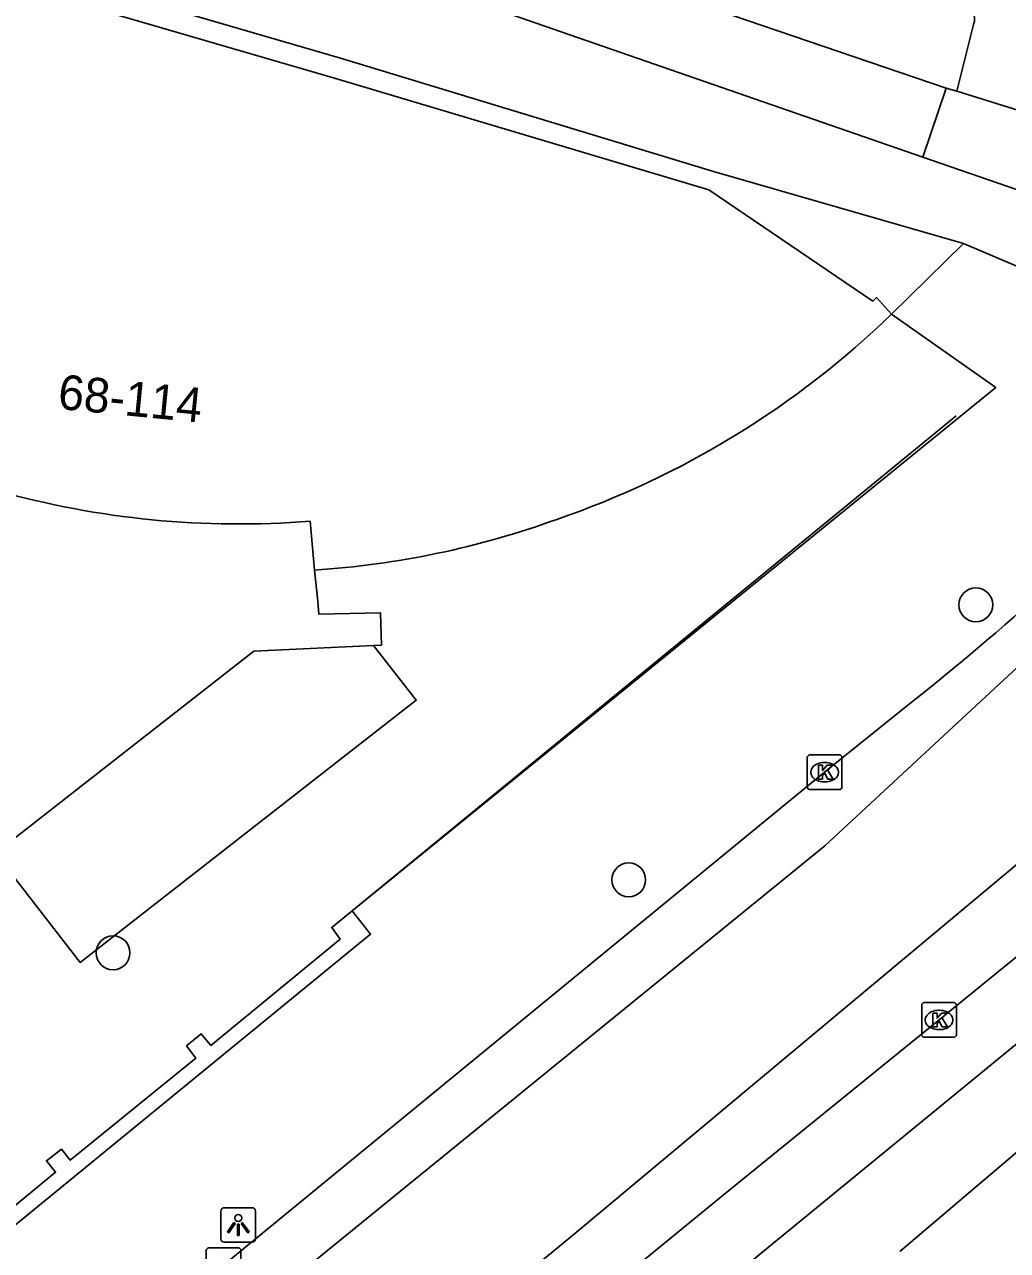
# Model space of a CAD drawing. Extents: x 161771 to 163125, y 382479 to 383177.
# Drawn here: x 162119.81 to 162148.2, y 383036.32 to 383071.72 of the extents above; entities that cross this region are included whole.
import ezdxf

# ---------------------------------------------------------------- set-up
doc = ezdxf.new("R2010")
doc.units = 0
for name, color, linetype in [('IMGEO_Boom', 7, 'Continuous'), ('IMGEO_Fietspad_gesloten', 7, 'Continuous'), ('IMGEO_Fietspad_open', 7, 'Continuous'), ('IMGEO_Groenvoorziening', 7, 'Continuous'), ('IMGEO_Hek', 7, 'Continuous'), ('IMGEO_Kolk', 7, 'Continuous'), ('IMGEO_Lichtpunt', 7, 'Continuous'), ('IMGEO_Muur', 7, 'Continuous'), ('IMGEO_Pand', 7, 'Continuous'), ('IMGEO_Pand_nummerreeks', 7, 'Continuous'), ('IMGEO_Rijbaan_lokaal_gesloten', 7, 'Continuous'), ('IMGEO_Voetpad_open', 7, 'Continuous')]:
    doc.layers.add(name, color=color, linetype=linetype)

msp = doc.modelspace()

# ---------------------------------------------------------------- linework, layer by layer
at = {"layer": 'IMGEO_Boom'}
for centre in [(162147.284, 383054.963), (162137.26, 383047.022), (162122.368, 383044.915)]:
    msp.add_circle(centre, 0.489, dxfattribs=at)
at = {"layer": 'IMGEO_Fietspad_gesloten'}
for points in [[(162114.9, 383079.294), (162127.757, 383076.182), (162129.761, 383075.563), (162130.935, 383075.168), (162146.429, 383069.887)], [(162145.752, 383067.892), (162131.194, 383072.949)], [(162146.429, 383069.887), (162145.752, 383067.892)]]:
    msp.add_lwpolyline(points, dxfattribs=at)
at = {"layer": 'IMGEO_Fietspad_open'}
for points in [[(162146.429, 383069.887), (162146.737, 383069.793)], [(162149.796, 383068.845), (162146.737, 383069.793)], [(162153.035, 383065.378), (162145.752, 383067.892)]]:
    msp.add_lwpolyline(points, dxfattribs=at)
at = {"layer": 'IMGEO_Groenvoorziening'}
msp.add_lwpolyline([(162129.888, 383053.79), (162131.122, 383052.209), (162121.422, 383044.636), (162118.96, 383047.789)], dxfattribs=at)
at = {"layer": 'IMGEO_Hek'}
msp.add_lwpolyline([(162129.276, 383046.131), (162146.715, 383060.424)], dxfattribs=at)
at = {"layer": 'IMGEO_Kolk'}
for p, q in [((162142.417, 383049.703), (162142.417, 383050.555)), ((162142.492, 383050.629), (162143.344, 383050.629)), ((162143.418, 383050.555), (162143.418, 383049.703)), ((162142.905, 383050.409), (162142.93, 383050.409)), ((162142.928, 383049.849), (162142.903, 383049.849)), ((162143.344, 383049.629), (162142.492, 383049.629)), ((162145.797, 383043.475), (162146.649, 383043.475)), ((162145.722, 383042.549), (162145.722, 383043.401)), ((162146.21, 383043.255), (162146.235, 383043.255)), ((162146.723, 383043.401), (162146.723, 383042.549)), ((162146.649, 383042.475), (162145.797, 383042.475)), ((162146.233, 383042.695), (162146.208, 383042.695)), ((162125.136, 383036.392), (162125.988, 383036.392)), ((162125.061, 383035.466), (162125.061, 383036.318)), ((162126.062, 383036.318), (162126.062, 383035.466))]:
    msp.add_line(p, q, dxfattribs=at)
for points in [[(162142.417, 383049.703), (162142.417, 383050.555)], [(162142.492, 383050.629), (162143.344, 383050.629)], [(162143.418, 383050.555), (162143.418, 383049.703)], [(162142.738, 383050.329), (162142.861, 383050.329), (162142.861, 383050.178), (162142.991, 383050.329), (162143.155, 383050.329), (162143.009, 383050.178), (162143.162, 383049.929), (162143.01, 383049.929), (162142.925, 383050.093), (162142.861, 383050.026), (162142.861, 383049.929), (162142.738, 383049.929), (162142.738, 383050.329)], [(162143.344, 383049.629), (162142.492, 383049.629)], [(162145.797, 383043.475), (162146.649, 383043.475)], [(162145.722, 383042.549), (162145.722, 383043.401)], [(162146.043, 383043.175), (162146.166, 383043.175), (162146.166, 383043.024), (162146.296, 383043.175), (162146.46, 383043.175), (162146.314, 383043.024), (162146.467, 383042.775), (162146.315, 383042.775), (162146.23, 383042.939), (162146.166, 383042.872), (162146.166, 383042.775), (162146.043, 383042.775), (162146.043, 383043.175)], [(162146.723, 383043.401), (162146.723, 383042.549)], [(162146.649, 383042.475), (162145.797, 383042.475)], [(162125.136, 383036.392), (162125.988, 383036.392)], [(162125.061, 383035.466), (162125.061, 383036.318)], [(162126.062, 383036.318), (162126.062, 383035.466)]]:
    msp.add_lwpolyline(points, dxfattribs=at)
for centre, start, end in [((162142.494, 383050.553), 91.552, 178.448), ((162142.494, 383050.553), 91.552, 178.448), ((162143.342, 383050.553), 1.552, 88.448), ((162143.342, 383050.553), 1.552, 88.448), ((162142.494, 383049.705), 181.552, 268.448), ((162142.494, 383049.705), 181.552, 268.448), ((162143.342, 383049.705), 271.552, 358.448), ((162143.342, 383049.705), 271.552, 358.448), ((162145.799, 383043.399), 91.552, 178.448), ((162145.799, 383043.399), 91.552, 178.448), ((162146.647, 383043.399), 1.552, 88.448), ((162146.647, 383043.399), 1.552, 88.448), ((162145.799, 383042.551), 181.552, 268.448), ((162145.799, 383042.551), 181.552, 268.448), ((162146.647, 383042.551), 271.552, 358.448), ((162146.647, 383042.551), 271.552, 358.448), ((162125.138, 383036.316), 91.552, 178.448), ((162125.138, 383036.316), 91.552, 178.448), ((162125.986, 383036.316), 1.552, 88.448), ((162125.986, 383036.316), 1.552, 88.448)]:
    msp.add_arc(centre, 0.0765, start, end, dxfattribs=at)
for centre, major_axis, ratio, start_param, end_param in [((162142.904, 383050.129), (-0.387, 0.002), 0.722429, 4.712389, 7.853982), ((162142.929, 383050.129), (-0.39, 0.002), 0.717154, 1.570796, 4.712389), ((162146.209, 383042.975), (-0.387, 0.002), 0.722429, 4.712389, 7.853982), ((162146.234, 383042.975), (-0.39, 0.002), 0.717154, 1.570796, 4.712389)]:
    msp.add_ellipse(centre, major_axis=major_axis, ratio=ratio, start_param=start_param, end_param=end_param, dxfattribs=at)
at = {"layer": 'IMGEO_Lichtpunt'}
for p, q in [((162125.484, 383037.458), (162125.484, 383036.651)), ((162125.484, 383037.458), (162125.484, 383036.651)), ((162126.386, 383037.553), (162125.578, 383037.553)), ((162126.386, 383037.553), (162125.578, 383037.553)), ((162126.48, 383036.651), (162126.48, 383037.458)), ((162126.48, 383036.651), (162126.48, 383037.458)), ((162125.578, 383036.557), (162126.386, 383036.557)), ((162125.578, 383036.557), (162126.386, 383036.557))]:
    msp.add_line(p, q, dxfattribs=at)
for points in [[(162125.858, 383037.122), (162125.897, 383037.094), (162125.709, 383036.832), (162125.671, 383036.859), (162125.858, 383037.122)], [(162126.07, 383037.094), (162126.108, 383037.121), (162126.295, 383036.859), (162126.256, 383036.831), (162126.07, 383037.094)], [(162125.96, 383037.074), (162126.007, 383037.074), (162126.007, 383036.752), (162125.96, 383036.752), (162125.96, 383037.074)]]:
    msp.add_lwpolyline(points, dxfattribs=at)
msp.add_circle((162125.983, 383037.256), 0.0994, dxfattribs=at)
for centre, start, end in [((162125.578, 383037.458), 90, 180), ((162125.578, 383037.458), 90, 180), ((162126.386, 383037.458), 0, 90), ((162126.386, 383037.458), 0, 90), ((162125.578, 383036.651), 180, 270), ((162125.578, 383036.651), 180, 270), ((162126.386, 383036.651), 270, 0), ((162126.386, 383036.651), 270, 360)]:
    msp.add_arc(centre, 0.0946, start, end, dxfattribs=at)
at = {"layer": 'IMGEO_Muur'}
for points in [[(162129.276, 383046.131), (162129.803, 383045.451), (162103.195, 383023.682)], [(162110.892, 383030.523), (162112.755, 383032.045), (162112.475, 383032.411), (162112.92, 383032.736), (162113.192, 383032.404), (162116.661, 383035.248), (162116.389, 383035.606), (162116.824, 383035.941), (162117.098, 383035.607), (162120.707, 383038.578), (162120.445, 383038.91), (162120.875, 383039.244), (162121.134, 383038.926), (162124.759, 383041.875), (162124.489, 383042.227), (162124.916, 383042.571), (162125.194, 383042.234), (162128.922, 383045.308), (162128.682, 383045.648), (162129.276, 383046.131)]]:
    msp.add_lwpolyline(points, dxfattribs=at)
at = {"layer": 'IMGEO_Pand'}
for points in [[(162144.848, 383063.353), (162144.413, 383063.834), (162144.308, 383063.735), (162139.57, 383066.948), (162128.762, 383070.172), (162118.164, 383073.264), (162107.636, 383076.364), (162107.576, 383076.123)], [(162128.064, 383057.381), (162128.188, 383055.968)]]:
    msp.add_lwpolyline(points, dxfattribs=at)
for centre, radius, start, end in [((162126.726, 383082.086), 26.064, 288.9269, 314.051), ((162125.999, 383083.064), 25.766, 254.254, 274.5967), ((162126.564, 383081.167), 25.251, 273.6864, 289.9497)]:
    msp.add_arc(centre, radius, start, end, dxfattribs=at)
at = {"layer": 'IMGEO_Rijbaan_lokaal_gesloten'}
for points in [[(162157.47, 383063.478), (162155.349, 383059.528), (162142.919, 383048.007), (162116.302, 383026.353), (162047.566, 382968.998), (162025.43, 382950.879), (161998, 382928.746), (161992.488, 382924.359), (161988.947, 382921.944), (161983.958, 382918.885), (161979.294, 382916.006)], [(162164.197, 383062.015), (162160.98, 383057.918), (162135.752, 383036.849), (162098.092, 383005.831), (162064.893, 382976.459), (162028.312, 382947.355), (161996.833, 382921.662), (161989.309, 382915.625), (161975.267, 382904.355), (161969.513, 382899.968), (161964.685, 382896.828), (161958.891, 382892.441), (161953.057, 382887.933), (161929.84, 382869.578), (161924.324, 382865.246), (161911.803, 382855.192)], [(162100.16, 383015.252), (162125.562, 383035.892), (162142.917, 383050.128), (162145.413, 383052.14)], [(162128.111, 383028.214), (162130.549, 383030.199), (162140.092, 383038.001), (162146.222, 383042.976), (162155.209, 383050.292)]]:
    msp.add_lwpolyline(points, dxfattribs=at)
msp.add_arc((162099.908, 383109.769), 73.429, 308.29544, 317.09113, dxfattribs=at)
at = {"layer": 'IMGEO_Voetpad_open'}
for points in [[(162146.928, 383065.401), (162139.708, 383067.473), (162128.934, 383070.747), (162118.368, 383073.832), (162107.762, 383076.863), (162097.71, 383079.345), (162086.971, 383081.997), (162076.72, 383084.528), (162066.004, 383087.223), (162045.075, 383092.367), (162034.344, 383095.026), (162024.1, 383097.528), (162013.373, 383100.204), (162003.395, 383102.633), (162002.719, 383102.888), (162002.455, 383102.987), (162001.558, 383103.439), (162000, 383104.393), (161999.536, 383104.682)], [(162146.737, 383069.793), (162147.221, 383071.722)], [(162144.848, 383063.353), (162146.928, 383065.401)], [(162146.928, 383065.401), (162155.226, 383061.863)], [(162129.276, 383046.131), (162139.734, 383054.635), (162147.862, 383061.244), (162144.848, 383063.353)], [(162129.888, 383053.79), (162130.122, 383053.801), (162130.091, 383054.737), (162128.309, 383054.695), (162128.28, 383055.066), (162128.188, 383055.968)], [(162118.96, 383047.789), (162126.431, 383053.622), (162129.888, 383053.79)], [(162131.484, 383028.377), (162156.968, 383049.251)], [(162145.09, 383036.286), (162148.535, 383039.215)]]:
    msp.add_lwpolyline(points, dxfattribs=at)
msp.add_arc((162146.765, 383071.878), 0.482, 341.1488, 66.2408, dxfattribs=at)

# ---------------------------------------------------------------- texts
at = {"layer": 'IMGEO_Pand_nummerreeks'}
msp.add_text('68-114', height=1, rotation=354.4251, dxfattribs=at).set_placement((162120.749, 383060.627))

doc.saveas('drawing.dxf')
